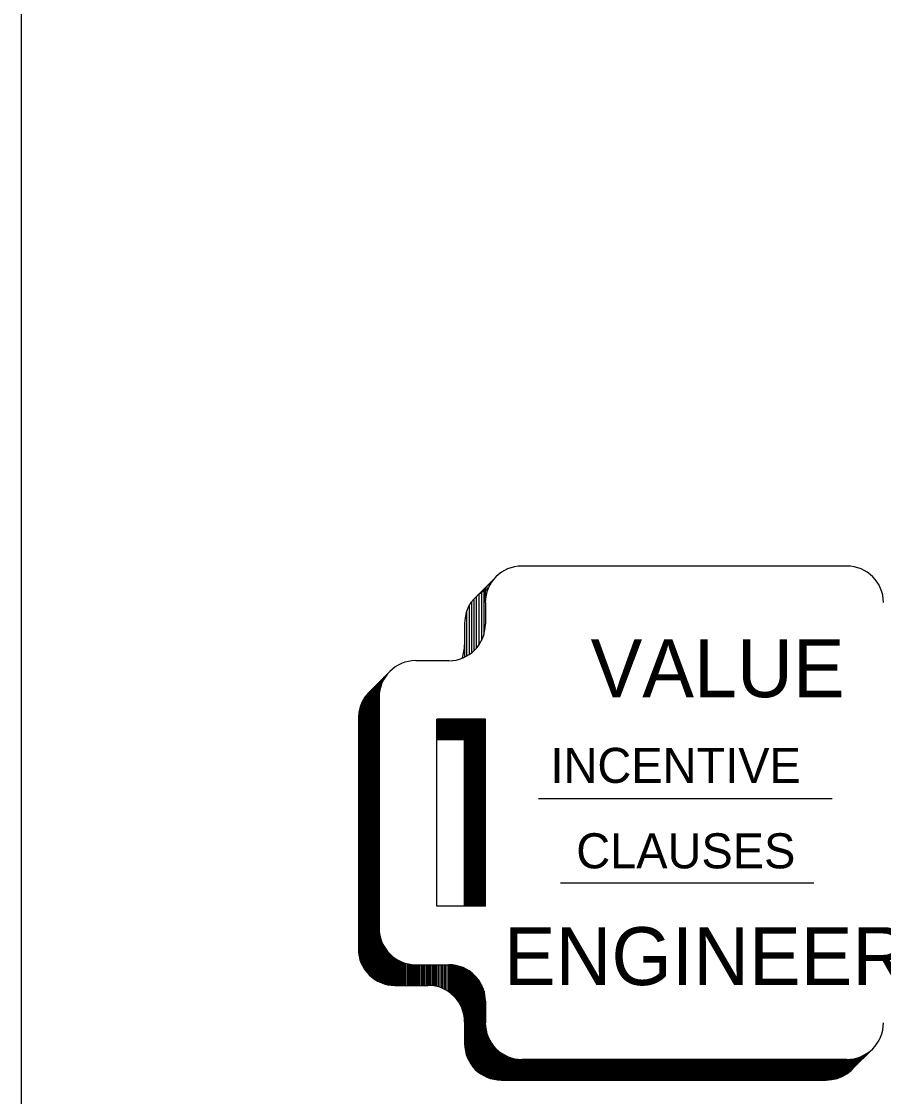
# Model space of a CAD drawing. Extents: x 44742.26 to 44749.63, y 44739 to 44741.19.
# Drawn here: x 44742.3563 to 44742.4509, y 44739.0661 to 44739.1842 of the extents above; entities that cross this region are included whole.
import ezdxf

# ---------------------------------------------------------------- set-up
doc = ezdxf.new("R2010")
doc.units = 0
for name, color, linetype in [('Level 2', 7, 'Continuous'), ('Level 7', 7, 'Continuous'), ('Level 9', 7, 'Continuous')]:
    doc.layers.add(name, color=color, linetype=linetype)

msp = doc.modelspace()

# ---------------------------------------------------------------- linework, layer by layer
at = {"layer": 'Level 2'}
for p, q in [((44742.40611, 44739.12091), (44742.40838, 44739.12318)), ((44742.40781, 44739.12245), (44742.40781, 44739.12261)), ((44742.40798, 44739.12271), (44742.40798, 44739.12278)), ((44742.40649, 44739.12129), (44742.40649, 44739.11567)), ((44742.40677, 44739.12158), (44742.40677, 44739.11616)), ((44742.40705, 44739.12185), (44742.40705, 44739.11685)), ((44742.40721, 44739.12034), (44742.40721, 44739.12201)), ((44742.4074, 44739.12157), (44742.4074, 44739.1222)), ((44742.40761, 44739.12209), (44742.40761, 44739.12241)), ((44742.40567, 44739.12039), (44742.40567, 44739.11481)), ((44742.40595, 44739.12073), (44742.40595, 44739.11505)), ((44742.40621, 44739.12101), (44742.40621, 44739.11532)), ((44742.40515, 44739.11937), (44742.40515, 44739.11447)), ((44742.40542, 44739.11999), (44742.40542, 44739.11463)), ((44742.40493, 44739.11807), (44742.40493, 44739.11436)), ((44742.39444, 44739.11051), (44742.39672, 44739.11278)), ((44742.39583, 44739.11143), (44742.39583, 44739.1119)), ((44742.39591, 44739.11162), (44742.39591, 44739.11198)), ((44742.39599, 44739.11177), (44742.39599, 44739.11205)), ((44742.39607, 44739.11192), (44742.39607, 44739.11213)), ((44742.39615, 44739.11205), (44742.39615, 44739.11221)), ((44742.39623, 44739.11218), (44742.39623, 44739.11229)), ((44742.39631, 44739.11229), (44742.39631, 44739.11237)), ((44742.3946, 44739.11066), (44742.3946, 44739.0793)), ((44742.39469, 44739.11076), (44742.39469, 44739.07921)), ((44742.3948, 44739.11086), (44742.3948, 44739.07913)), ((44742.39493, 44739.11099), (44742.39493, 44739.07904)), ((44742.39506, 44739.11113), (44742.39506, 44739.07894)), ((44742.39518, 44739.11124), (44742.39518, 44739.07887)), ((44742.39528, 44739.11134), (44742.39528, 44739.0788)), ((44742.39538, 44739.11145), (44742.39538, 44739.07875)), ((44742.39546, 44739.11152), (44742.39546, 44739.07871)), ((44742.39555, 44739.10994), (44742.39555, 44739.11161)), ((44742.39563, 44739.11077), (44742.39563, 44739.1117)), ((44742.39575, 44739.11119), (44742.39575, 44739.11181)), ((44742.39374, 44739.10954), (44742.39374, 44739.0804)), ((44742.39387, 44739.10977), (44742.39387, 44739.08018)), ((44742.39399, 44739.10996), (44742.39399, 44739.07999)), ((44742.39413, 44739.11015), (44742.39413, 44739.0798)), ((44742.39424, 44739.11028), (44742.39424, 44739.07966)), ((44742.39435, 44739.1104), (44742.39435, 44739.07954)), ((44742.39446, 44739.11052), (44742.39446, 44739.07943)), ((44742.39338, 44739.1086), (44742.39338, 44739.08134)), ((44742.39351, 44739.10901), (44742.39351, 44739.08093)), ((44742.39363, 44739.10933), (44742.39363, 44739.08062)), ((44742.39327, 44739.10766), (44742.39327, 44739.08228)), ((44742.40721, 44739.10742), (44742.40189, 44739.10742)), ((44742.40721, 44739.10732), (44742.40189, 44739.10732)), ((44742.40721, 44739.1072), (44742.40189, 44739.1072)), ((44742.40721, 44739.10753), (44742.40493, 44739.10526)), ((44742.40721, 44739.10708), (44742.40189, 44739.10708)), ((44742.40721, 44739.10695), (44742.40189, 44739.10695)), ((44742.40721, 44739.10683), (44742.40189, 44739.10683)), ((44742.40721, 44739.10671), (44742.40189, 44739.10671)), ((44742.40721, 44739.10658), (44742.40189, 44739.10658)), ((44742.40721, 44739.10647), (44742.40189, 44739.10647)), ((44742.40721, 44739.10635), (44742.40189, 44739.10635)), ((44742.40721, 44739.10623), (44742.40189, 44739.10623)), ((44742.40721, 44739.10611), (44742.40189, 44739.10611)), ((44742.40721, 44739.106), (44742.40189, 44739.106)), ((44742.40721, 44739.10591), (44742.40189, 44739.10591)), ((44742.40721, 44739.10579), (44742.40189, 44739.10579)), ((44742.40721, 44739.10569), (44742.40189, 44739.10569)), ((44742.40721, 44739.10558), (44742.40189, 44739.10558)), ((44742.40721, 44739.10549), (44742.40189, 44739.10549)), ((44742.40721, 44739.10537), (44742.40189, 44739.10537)), ((44742.40493, 44739.10526), (44742.40189, 44739.10526)), ((44742.40493, 44739.08697), (44742.40493, 44739.10526)), ((44742.40505, 44739.08697), (44742.40505, 44739.10537)), ((44742.40514, 44739.08697), (44742.40514, 44739.10537)), ((44742.40523, 44739.08697), (44742.40523, 44739.10537)), ((44742.40531, 44739.08697), (44742.40531, 44739.10537)), ((44742.40543, 44739.08697), (44742.40543, 44739.10537)), ((44742.40554, 44739.08697), (44742.40554, 44739.10537)), ((44742.40565, 44739.08697), (44742.40565, 44739.10537)), ((44742.40573, 44739.08697), (44742.40573, 44739.10537)), ((44742.40586, 44739.08697), (44742.40586, 44739.10537)), ((44742.40596, 44739.08697), (44742.40596, 44739.10537)), ((44742.40605, 44739.08697), (44742.40605, 44739.10537)), ((44742.40616, 44739.08697), (44742.40616, 44739.10537)), ((44742.40626, 44739.08697), (44742.40626, 44739.10537)), ((44742.40638, 44739.08697), (44742.40638, 44739.10537)), ((44742.40648, 44739.08697), (44742.40648, 44739.10537)), ((44742.40657, 44739.08697), (44742.40657, 44739.10537)), ((44742.40669, 44739.08697), (44742.40669, 44739.10537)), ((44742.40681, 44739.08697), (44742.40681, 44739.10537)), ((44742.40693, 44739.08697), (44742.40693, 44739.10537)), ((44742.40702, 44739.08697), (44742.40702, 44739.10537)), ((44742.40712, 44739.08697), (44742.40712, 44739.10537)), ((44742.3956, 44739.08389), (44742.3956, 44739.07864)), ((44742.39573, 44739.08335), (44742.39573, 44739.07858)), ((44742.39585, 44739.08302), (44742.39585, 44739.07853)), ((44742.39597, 44739.08276), (44742.39597, 44739.07849)), ((44742.39612, 44739.08249), (44742.39612, 44739.07844)), ((44742.39622, 44739.08233), (44742.39622, 44739.07841)), ((44742.39632, 44739.08218), (44742.39632, 44739.07839)), ((44742.39646, 44739.082), (44742.39646, 44739.07836)), ((44742.39657, 44739.08187), (44742.39657, 44739.07833)), ((44742.39669, 44739.08174), (44742.39669, 44739.07832)), ((44742.39681, 44739.08162), (44742.39681, 44739.07829)), ((44742.39693, 44739.08152), (44742.39693, 44739.07828)), ((44742.39705, 44739.08142), (44742.39705, 44739.07827)), ((44742.39718, 44739.08132), (44742.39718, 44739.07827)), ((44742.3973, 44739.08123), (44742.3973, 44739.07827)), ((44742.39742, 44739.08116), (44742.39742, 44739.07827)), ((44742.39755, 44739.08109), (44742.39755, 44739.07827)), ((44742.39769, 44739.08101), (44742.39769, 44739.07827)), ((44742.39779, 44739.08095), (44742.39779, 44739.07827)), ((44742.39786, 44739.08092), (44742.39786, 44739.07827)), ((44742.39796, 44739.08087), (44742.39796, 44739.07827)), ((44742.39807, 44739.08083), (44742.39807, 44739.07827)), ((44742.3982, 44739.08078), (44742.3982, 44739.07827)), ((44742.39832, 44739.08073), (44742.39832, 44739.07827)), ((44742.39844, 44739.0807), (44742.39844, 44739.07827)), ((44742.39861, 44739.08065), (44742.39861, 44739.07827)), ((44742.39875, 44739.08062), (44742.39875, 44739.07827)), ((44742.39887, 44739.0806), (44742.39887, 44739.07827)), ((44742.39896, 44739.08059), (44742.39896, 44739.07827)), ((44742.39908, 44739.08057), (44742.39908, 44739.07827)), ((44742.39918, 44739.08056), (44742.39918, 44739.07827)), ((44742.39927, 44739.08055), (44742.39927, 44739.07827)), ((44742.39938, 44739.08054), (44742.39938, 44739.07827)), ((44742.39951, 44739.08054), (44742.39951, 44739.07827)), ((44742.39963, 44739.08054), (44742.39963, 44739.07827)), ((44742.39977, 44739.08054), (44742.39977, 44739.07827)), ((44742.39991, 44739.08054), (44742.39991, 44739.07827)), ((44742.40003, 44739.08054), (44742.40003, 44739.07827)), ((44742.40019, 44739.08054), (44742.40019, 44739.07827)), ((44742.40032, 44739.08054), (44742.40032, 44739.07827)), ((44742.40044, 44739.08054), (44742.40044, 44739.07827)), ((44742.40058, 44739.08054), (44742.40058, 44739.07827)), ((44742.40073, 44739.08054), (44742.40073, 44739.07827)), ((44742.40088, 44739.08054), (44742.40088, 44739.07827)), ((44742.40103, 44739.08054), (44742.40103, 44739.07827)), ((44742.40118, 44739.08054), (44742.40118, 44739.07827)), ((44742.40136, 44739.08054), (44742.40136, 44739.07824)), ((44742.40148, 44739.08054), (44742.40148, 44739.07823)), ((44742.40159, 44739.08054), (44742.40159, 44739.07821)), ((44742.40169, 44739.08054), (44742.40169, 44739.07819)), ((44742.40186, 44739.08054), (44742.40186, 44739.07815)), ((44742.40204, 44739.08054), (44742.40204, 44739.07811)), ((44742.40222, 44739.08054), (44742.40222, 44739.07805)), ((44742.4024, 44739.08054), (44742.4024, 44739.07799)), ((44742.40255, 44739.08054), (44742.40255, 44739.07792)), ((44742.40273, 44739.08054), (44742.40273, 44739.07784)), ((44742.40286, 44739.08054), (44742.40286, 44739.07777)), ((44742.40307, 44739.08054), (44742.40307, 44739.07764)), ((44742.40324, 44739.08054), (44742.40324, 44739.07753)), ((44742.40333, 44739.08054), (44742.40333, 44739.07746)), ((44742.40348, 44739.08054), (44742.40348, 44739.07734)), ((44742.4036, 44739.08052), (44742.4036, 44739.07724)), ((44742.40373, 44739.0805), (44742.40373, 44739.07712)), ((44742.40385, 44739.08048), (44742.40385, 44739.077)), ((44742.40394, 44739.08047), (44742.40394, 44739.0769)), ((44742.40408, 44739.08044), (44742.40408, 44739.07673)), ((44742.40421, 44739.08041), (44742.40421, 44739.07655)), ((44742.40436, 44739.08037), (44742.40436, 44739.07632)), ((44742.40449, 44739.08032), (44742.40449, 44739.07608)), ((44742.40461, 44739.08028), (44742.40461, 44739.07582)), ((44742.40474, 44739.08023), (44742.40474, 44739.07548)), ((44742.40488, 44739.08017), (44742.40488, 44739.07492)), ((44742.40498, 44739.08012), (44742.40498, 44739.07126)), ((44742.40511, 44739.08005), (44742.40511, 44739.0707)), ((44742.40524, 44739.07998), (44742.40524, 44739.07035)), ((44742.40536, 44739.07991), (44742.40536, 44739.07008)), ((44742.40548, 44739.07983), (44742.40548, 44739.06986)), ((44742.4056, 44739.07974), (44742.4056, 44739.06966)), ((44742.40574, 44739.07963), (44742.40574, 44739.06947)), ((44742.40584, 44739.07954), (44742.40584, 44739.06933)), ((44742.40596, 44739.07943), (44742.40596, 44739.0692)), ((44742.40607, 44739.07933), (44742.40607, 44739.06909)), ((44742.4062, 44739.07919), (44742.4062, 44739.06896)), ((44742.40632, 44739.07905), (44742.40632, 44739.06885)), ((44742.40645, 44739.07887), (44742.40645, 44739.06873)), ((44742.39729, 44739.07827), (44742.40092, 44739.07827)), ((44742.40658, 44739.07868), (44742.40658, 44739.06864)), ((44742.40669, 44739.07851), (44742.40669, 44739.06856)), ((44742.40678, 44739.07832), (44742.40678, 44739.0685)), ((44742.40686, 44739.07815), (44742.40686, 44739.06845)), ((44742.40697, 44739.0779), (44742.40697, 44739.06839)), ((44742.40706, 44739.07762), (44742.40706, 44739.06834)), ((44742.40713, 44739.07732), (44742.40713, 44739.0683)), ((44742.40493, 44739.07425), (44742.40493, 44739.07188)), ((44742.40722, 44739.0739), (44742.40722, 44739.06826)), ((44742.40733, 44739.07317), (44742.40733, 44739.06821)), ((44742.40743, 44739.07283), (44742.40743, 44739.06816)), ((44742.40752, 44739.0726), (44742.40752, 44739.06813)), ((44742.40762, 44739.07239), (44742.40762, 44739.06809)), ((44742.4077, 44739.07223), (44742.4077, 44739.06807)), ((44742.40781, 44739.07204), (44742.40781, 44739.06803)), ((44742.40791, 44739.07188), (44742.40791, 44739.068)), ((44742.40803, 44739.07172), (44742.40803, 44739.06797)), ((44742.40811, 44739.07162), (44742.40811, 44739.06795)), ((44742.40822, 44739.07149), (44742.40822, 44739.06793)), ((44742.40828, 44739.07142), (44742.40828, 44739.06792)), ((44742.40837, 44739.07133), (44742.40837, 44739.06791)), ((44742.40847, 44739.07123), (44742.40847, 44739.0679)), ((44742.40854, 44739.07117), (44742.40854, 44739.06789)), ((44742.40859, 44739.07113), (44742.40859, 44739.06788)), ((44742.40865, 44739.07108), (44742.40865, 44739.06787)), ((44742.40873, 44739.07101), (44742.40873, 44739.06787)), ((44742.40885, 44739.07092), (44742.40885, 44739.06787)), ((44742.40898, 44739.07083), (44742.40898, 44739.06787)), ((44742.40909, 44739.07076), (44742.40909, 44739.06787)), ((44742.40922, 44739.07068), (44742.40922, 44739.06787)), ((44742.40934, 44739.07061), (44742.40934, 44739.06787)), ((44742.40946, 44739.07055), (44742.40946, 44739.06787)), ((44742.40955, 44739.0705), (44742.40955, 44739.06787)), ((44742.44749, 44739.06904), (44742.44976, 44739.07131)), ((44742.44857, 44739.07011), (44742.44857, 44739.07049)), ((44742.44865, 44739.07019), (44742.44865, 44739.07053)), ((44742.44874, 44739.07028), (44742.44874, 44739.07057)), ((44742.44881, 44739.07036), (44742.44881, 44739.07061)), ((44742.44888, 44739.07043), (44742.44888, 44739.07065)), ((44742.44895, 44739.0705), (44742.44895, 44739.07069)), ((44742.44903, 44739.07058), (44742.44903, 44739.07074)), ((44742.44911, 44739.07066), (44742.44911, 44739.07079)), ((44742.44918, 44739.07073), (44742.44918, 44739.07084)), ((44742.44926, 44739.0708), (44742.44926, 44739.07089)), ((44742.44933, 44739.07088), (44742.44933, 44739.07094)), ((44742.40967, 44739.07045), (44742.40967, 44739.06787)), ((44742.40979, 44739.0704), (44742.40979, 44739.06787)), ((44742.40992, 44739.07036), (44742.40992, 44739.06787)), ((44742.41005, 44739.07031), (44742.41005, 44739.06787)), ((44742.41019, 44739.07027), (44742.41019, 44739.06787)), ((44742.41033, 44739.07023), (44742.41033, 44739.06787)), ((44742.41045, 44739.07021), (44742.41045, 44739.06787)), ((44742.41059, 44739.07019), (44742.41059, 44739.06787)), ((44742.41072, 44739.07017), (44742.41072, 44739.06787)), ((44742.41085, 44739.07015), (44742.41085, 44739.06787)), ((44742.411, 44739.07015), (44742.411, 44739.06787)), ((44742.41113, 44739.07014), (44742.41113, 44739.06787)), ((44742.41113, 44739.07008), (44742.44465, 44739.07008)), ((44742.41113, 44739.07004), (44742.44465, 44739.07004)), ((44742.41113, 44739.07), (44742.44465, 44739.07)), ((44742.41113, 44739.06995), (44742.44465, 44739.06995)), ((44742.41113, 44739.06988), (44742.44465, 44739.06988)), ((44742.41113, 44739.06981), (44742.44465, 44739.06981)), ((44742.41113, 44739.06974), (44742.44465, 44739.06974)), ((44742.41113, 44739.06967), (44742.44465, 44739.06967)), ((44742.41113, 44739.0696), (44742.44465, 44739.0696)), ((44742.41113, 44739.06953), (44742.44465, 44739.06953)), ((44742.41113, 44739.06946), (44742.44465, 44739.06946)), ((44742.41113, 44739.06938), (44742.44465, 44739.06938)), ((44742.41113, 44739.06931), (44742.44465, 44739.06931)), ((44742.44465, 44739.06786), (44742.44465, 44739.07014)), ((44742.44473, 44739.06786), (44742.44473, 44739.07014)), ((44742.4448, 44739.06786), (44742.4448, 44739.07014)), ((44742.44486, 44739.06787), (44742.44486, 44739.07014)), ((44742.44497, 44739.06788), (44742.44497, 44739.07014)), ((44742.44505, 44739.06789), (44742.44505, 44739.07014)), ((44742.44514, 44739.0679), (44742.44514, 44739.07014)), ((44742.44522, 44739.06791), (44742.44522, 44739.07014)), ((44742.44531, 44739.06792), (44742.44531, 44739.07014)), ((44742.44539, 44739.06794), (44742.44539, 44739.07014)), ((44742.44548, 44739.06795), (44742.44548, 44739.07014)), ((44742.44557, 44739.06797), (44742.44557, 44739.07014)), ((44742.44566, 44739.06799), (44742.44566, 44739.07014)), ((44742.44577, 44739.06803), (44742.44577, 44739.07014)), ((44742.44589, 44739.06807), (44742.44589, 44739.07014)), ((44742.44599, 44739.0681), (44742.44599, 44739.07014)), ((44742.44608, 44739.06813), (44742.44608, 44739.07014)), ((44742.44619, 44739.06817), (44742.44619, 44739.07014)), ((44742.44629, 44739.06822), (44742.44629, 44739.07014)), ((44742.44638, 44739.06826), (44742.44638, 44739.07014)), ((44742.4465, 44739.06832), (44742.4465, 44739.07014)), ((44742.44662, 44739.06839), (44742.44662, 44739.07014)), ((44742.44673, 44739.06845), (44742.44673, 44739.07014)), ((44742.44685, 44739.06852), (44742.44685, 44739.07014)), ((44742.44696, 44739.0686), (44742.44696, 44739.07014)), ((44742.44706, 44739.06868), (44742.44706, 44739.07014)), ((44742.44718, 44739.06876), (44742.44718, 44739.07014)), ((44742.4473, 44739.06886), (44742.4473, 44739.07015)), ((44742.44741, 44739.06897), (44742.44741, 44739.07017)), ((44742.44751, 44739.06905), (44742.44751, 44739.07018)), ((44742.44761, 44739.06916), (44742.44761, 44739.07019)), ((44742.44769, 44739.06924), (44742.44769, 44739.07021)), ((44742.44779, 44739.06933), (44742.44779, 44739.07023)), ((44742.44787, 44739.06942), (44742.44787, 44739.07025)), ((44742.44796, 44739.0695), (44742.44796, 44739.07027)), ((44742.44805, 44739.0696), (44742.44805, 44739.0703)), ((44742.44812, 44739.06966), (44742.44812, 44739.07032)), ((44742.4482, 44739.06974), (44742.4482, 44739.07035)), ((44742.44827, 44739.06982), (44742.44827, 44739.07037)), ((44742.44835, 44739.0699), (44742.44835, 44739.0704)), ((44742.4484, 44739.06995), (44742.4484, 44739.07042)), ((44742.44849, 44739.07004), (44742.44849, 44739.07046)), ((44742.41113, 44739.06925), (44742.44465, 44739.06925)), ((44742.41113, 44739.06917), (44742.44465, 44739.06917)), ((44742.41113, 44739.06911), (44742.44465, 44739.06911)), ((44742.41113, 44739.06905), (44742.44465, 44739.06905)), ((44742.41113, 44739.06897), (44742.44465, 44739.06897)), ((44742.41113, 44739.0689), (44742.44465, 44739.0689)), ((44742.41113, 44739.06882), (44742.44465, 44739.06882)), ((44742.41113, 44739.06874), (44742.44465, 44739.06874)), ((44742.41113, 44739.06866), (44742.44465, 44739.06866)), ((44742.41113, 44739.06859), (44742.44465, 44739.06859)), ((44742.41113, 44739.0685), (44742.44465, 44739.0685)), ((44742.41113, 44739.06842), (44742.44465, 44739.06842)), ((44742.41113, 44739.06833), (44742.44465, 44739.06833)), ((44742.41113, 44739.06824), (44742.44465, 44739.06824)), ((44742.41113, 44739.06815), (44742.44465, 44739.06815)), ((44742.40895, 44739.06786), (44742.44465, 44739.06786)), ((44742.41113, 44739.06806), (44742.44465, 44739.06806)), ((44742.41113, 44739.06797), (44742.44465, 44739.06797))]:
    msp.add_line(p, q, dxfattribs=at)
for centre, start, end in [((44742.40895, 44739.11807), 111.4079, 180), ((44742.40091, 44739.1157), 338.5921, 0), ((44742.39728, 44739.10767), 111.4079, 180), ((44742.39728, 44739.08228), 180, 270), ((44742.40091, 44739.07425), 0, 90), ((44742.40895, 44739.07188), 180, 270), ((44742.44464, 44739.07188), 270, 338.5921)]:
    msp.add_arc(centre, 0.00402, start, end, dxfattribs=at)
at = {"layer": 'Level 7'}
for p, q in [((44742.44692, 44739.12436), (44742.41122, 44739.12436)), ((44742.40721, 44739.12034), (44742.40721, 44739.11797)), ((44742.40319, 44739.11395), (44742.39956, 44739.11395)), ((44742.39555, 44739.10994), (44742.39555, 44739.08456)), ((44742.40721, 44739.10753), (44742.40189, 44739.10753)), ((44742.40189, 44739.08697), (44742.40189, 44739.10753)), ((44742.40721, 44739.08697), (44742.40721, 44739.10753)), ((44742.41303, 44739.0988), (44742.44528, 44739.0988)), ((44742.41546, 44739.08954), (44742.44329, 44739.08954)), ((44742.40721, 44739.08697), (44742.40189, 44739.08697)), ((44742.39956, 44739.08054), (44742.40319, 44739.08054)), ((44742.40721, 44739.07652), (44742.40721, 44739.07415)), ((44742.41122, 44739.07014), (44742.44692, 44739.07014))]:
    msp.add_line(p, q, dxfattribs=at)
for centre, start, end in [((44742.41122, 44739.12034), 90, 180), ((44742.44691, 44739.12034), 0, 90), ((44742.40319, 44739.11797), 270, 0), ((44742.39956, 44739.10994), 90, 180), ((44742.39956, 44739.08456), 180, 270), ((44742.40319, 44739.07652), 0, 90), ((44742.41122, 44739.07415), 180, 270), ((44742.44691, 44739.07415), 270, 0)]:
    msp.add_arc(centre, 0.00402, start, end, dxfattribs=at)
at = {"layer": 'Level 9'}
msp.add_line((44742.35627, 44739.03544), (44742.35627, 44741.15596), dxfattribs=at)

# ---------------------------------------------------------------- texts
at = {"layer": 'Level 2'}
for s, height, p in [('VALUE', 0.006361, (44742.41877, 44739.10994)), ('INCENTIVE', 0.003855, (44742.41436, 44739.10052)), ('CLAUSES', 0.003855, (44742.41719, 44739.09113)), ('ENGINEERING', 0.0063611, (44742.40924, 44739.0783))]:
    msp.add_text(s, height=height, dxfattribs=at).set_placement(p)

doc.saveas('drawing.dxf')
